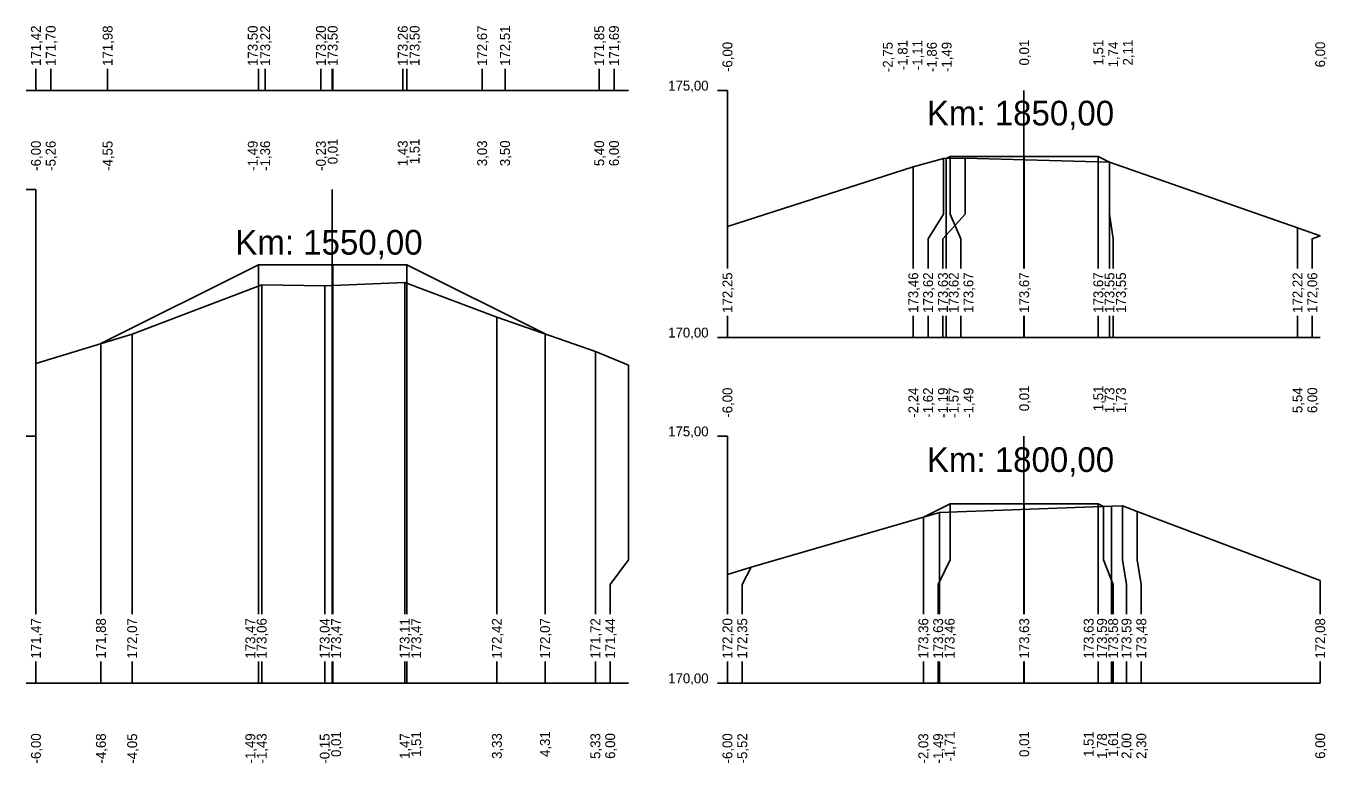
# Model space of a CAD drawing. Extents: x -614174 to -599765, y -1185887 to -1181080.
# Drawn here: x -600997.63 to -600971.29, y -1184434.96 to -1184420.03 of the extents above; entities that cross this region are included whole.
import ezdxf

# ---------------------------------------------------------------- set-up
doc = ezdxf.new("R2010")
doc.units = 0
for name, color, linetype in [('11', 7, 'Continuous'), ('16', 7, 'Continuous'), ('21', 7, 'Continuous'), ('28', 7, 'Continuous'), ('59', 7, 'Continuous'), ('8', 7, 'Continuous')]:
    doc.layers.add(name, color=color, linetype=linetype)

msp = doc.modelspace()

# ---------------------------------------------------------------- linework, layer by layer
for points in [[(-600983.427, -1184424.095), (-600979.665, -1184422.887), (-600979.052, -1184422.719), (-600978.616, -1184422.709), (-600975.693, -1184422.789), (-600971.887, -1184424.12), (-600971.427, -1184424.281)], [(-600979.001, -1184422.717), (-600978.919, -1184422.677), (-600977.419, -1184422.677), (-600975.919, -1184422.677), (-600975.695, -1184422.789)], [(-600979.001, -1184422.717), (-600979.001, -1184422.717), (-600979.001, -1184422.717)], [(-600978.919, -1184422.677), (-600978.919, -1184422.677), (-600978.919, -1184422.677)], [(-600977.419, -1184422.677), (-600977.419, -1184422.677), (-600977.419, -1184422.677)], [(-600975.919, -1184422.677), (-600975.919, -1184422.677), (-600975.919, -1184422.677)], [(-600996.111, -1184426.465), (-600992.919, -1184424.87), (-600991.419, -1184424.87), (-600989.919, -1184424.87), (-600987.12, -1184426.269)], [(-600992.919, -1184424.87), (-600992.919, -1184424.87), (-600992.919, -1184424.87)], [(-600991.419, -1184424.87), (-600991.419, -1184424.87), (-600991.419, -1184424.87)], [(-600989.919, -1184424.87), (-600989.919, -1184424.87), (-600989.919, -1184424.87)], [(-600997.427, -1184426.868), (-600995.478, -1184426.271), (-600992.856, -1184425.278), (-600991.58, -1184425.298), (-600989.96, -1184425.23), (-600988.095, -1184425.927), (-600986.101, -1184426.627), (-600985.427, -1184426.902)], [(-600996.11, -1184426.465), (-600996.111, -1184426.465), (-600996.111, -1184426.465)], [(-600983.427, -1184431.139), (-600982.948, -1184430.989), (-600979.134, -1184429.885), (-600975.649, -1184429.755), (-600975.429, -1184429.752), (-600975.13, -1184429.866), (-600971.427, -1184431.26)], [(-600979.461, -1184429.98), (-600978.919, -1184429.709), (-600977.419, -1184429.709), (-600975.919, -1184429.709), (-600975.814, -1184429.761)], [(-600978.919, -1184429.709), (-600978.919, -1184429.709), (-600978.919, -1184429.709)], [(-600977.419, -1184429.709), (-600977.419, -1184429.709), (-600977.419, -1184429.709)], [(-600975.919, -1184429.709), (-600975.919, -1184429.709), (-600975.919, -1184429.709)], [(-600979.462, -1184429.98), (-600979.461, -1184429.98), (-600979.461, -1184429.98)]]:
    msp.add_lwpolyline(points)
at = {"layer": '11'}
for points in [[(-600997.427, -1184420.902), (-600997.427, -1184421.342)], [(-600997.127, -1184420.902), (-600997.127, -1184421.342)], [(-600995.975, -1184420.902), (-600995.975, -1184421.342)], [(-600992.919, -1184420.902), (-600992.919, -1184421.342)], [(-600992.785, -1184420.902), (-600992.785, -1184421.342)], [(-600991.657, -1184420.902), (-600991.657, -1184421.342)], [(-600991.419, -1184420.902), (-600991.419, -1184421.342)], [(-600990, -1184420.902), (-600990, -1184421.342)], [(-600989.919, -1184420.902), (-600989.919, -1184421.342)], [(-600988.393, -1184420.902), (-600988.393, -1184421.342)], [(-600987.93, -1184420.902), (-600987.93, -1184421.342)], [(-600986.023, -1184420.902), (-600986.023, -1184421.342)], [(-600985.723, -1184420.902), (-600985.723, -1184421.342)], [(-600979.665, -1184422.887), (-600979.665, -1184423.842), (-600979.665, -1184424.342), (-600979.665, -1184424.944)], [(-600979.052, -1184422.719), (-600979.052, -1184423.842), (-600979.365, -1184424.342), (-600979.365, -1184424.944)], [(-600978.616, -1184422.709), (-600978.616, -1184423.842), (-600979.065, -1184424.342), (-600979.065, -1184424.944)], [(-600979.001, -1184422.717), (-600979.001, -1184423.842), (-600979.001, -1184424.342), (-600979.001, -1184424.944)], [(-600978.919, -1184422.677), (-600978.919, -1184423.842), (-600978.701, -1184424.342), (-600978.701, -1184424.944)], [(-600977.419, -1184422.677), (-600977.419, -1184423.842), (-600977.419, -1184424.342), (-600977.419, -1184424.944)], [(-600975.919, -1184422.677), (-600975.919, -1184423.842), (-600975.919, -1184424.342), (-600975.919, -1184424.944)], [(-600975.695, -1184422.789), (-600975.695, -1184423.842), (-600975.619, -1184424.342), (-600975.619, -1184424.944)], [(-600975.693, -1184422.789), (-600975.693, -1184423.842), (-600975.693, -1184424.342), (-600975.693, -1184424.944)], [(-600983.427, -1184424.095), (-600983.427, -1184423.842), (-600983.427, -1184424.342), (-600983.427, -1184424.944)], [(-600971.887, -1184424.12), (-600971.887, -1184424.342), (-600971.887, -1184424.944)], [(-600971.427, -1184424.281), (-600971.427, -1184424.281), (-600971.587, -1184424.342), (-600971.587, -1184424.944)], [(-600992.919, -1184424.87), (-600992.919, -1184430.842), (-600992.919, -1184431.342), (-600992.919, -1184431.944)], [(-600991.419, -1184424.87), (-600991.419, -1184430.842), (-600991.419, -1184431.342), (-600991.419, -1184431.944)], [(-600989.919, -1184424.87), (-600989.919, -1184430.842), (-600989.919, -1184431.342), (-600989.919, -1184431.944)], [(-600992.856, -1184425.278), (-600992.856, -1184430.842), (-600992.856, -1184431.342), (-600992.856, -1184431.944)], [(-600989.96, -1184425.23), (-600989.96, -1184430.842), (-600989.96, -1184431.342), (-600989.96, -1184431.944)], [(-600991.58, -1184425.298), (-600991.58, -1184430.842), (-600991.58, -1184431.342), (-600991.58, -1184431.944)], [(-600988.095, -1184425.927), (-600988.095, -1184430.842), (-600988.095, -1184431.342), (-600988.095, -1184431.944)], [(-600983.427, -1184425.902), (-600983.427, -1184426.342)], [(-600979.665, -1184425.902), (-600979.665, -1184426.342)], [(-600979.365, -1184425.902), (-600979.365, -1184426.342)], [(-600979.065, -1184425.902), (-600979.065, -1184426.342)], [(-600979.001, -1184425.902), (-600979.001, -1184426.342)], [(-600978.701, -1184425.902), (-600978.701, -1184426.342)], [(-600977.419, -1184425.902), (-600977.419, -1184426.342)], [(-600975.919, -1184425.902), (-600975.919, -1184426.342)], [(-600975.693, -1184425.902), (-600975.693, -1184426.342)], [(-600975.619, -1184425.902), (-600975.619, -1184426.342)], [(-600971.887, -1184425.902), (-600971.887, -1184426.342)], [(-600971.587, -1184425.902), (-600971.587, -1184426.342)], [(-600995.478, -1184426.271), (-600995.478, -1184430.842), (-600995.478, -1184431.342), (-600995.478, -1184431.944)], [(-600987.12, -1184426.269), (-600987.12, -1184430.842), (-600987.12, -1184431.342), (-600987.12, -1184431.944)], [(-600996.111, -1184426.465), (-600996.111, -1184430.842), (-600996.111, -1184431.342), (-600996.111, -1184431.944)], [(-600997.427, -1184426.868), (-600997.427, -1184430.842), (-600997.427, -1184431.342), (-600997.427, -1184431.944)], [(-600986.101, -1184426.627), (-600986.101, -1184430.842), (-600986.101, -1184431.342), (-600986.101, -1184431.944)], [(-600985.427, -1184426.902), (-600985.427, -1184430.842), (-600985.801, -1184431.342), (-600985.801, -1184431.944)], [(-600978.919, -1184429.709), (-600978.919, -1184430.842), (-600979.161, -1184431.342), (-600979.161, -1184431.944)], [(-600977.419, -1184429.709), (-600977.419, -1184430.842), (-600977.419, -1184431.342), (-600977.419, -1184431.944)], [(-600975.919, -1184429.709), (-600975.919, -1184430.842), (-600975.919, -1184431.342), (-600975.919, -1184431.944)], [(-600975.814, -1184429.761), (-600975.814, -1184430.842), (-600975.619, -1184431.342), (-600975.619, -1184431.944)], [(-600975.649, -1184429.755), (-600975.649, -1184430.842), (-600975.649, -1184431.342), (-600975.649, -1184431.944)], [(-600975.429, -1184429.752), (-600975.429, -1184430.842), (-600975.349, -1184431.342), (-600975.349, -1184431.944)], [(-600979.461, -1184429.98), (-600979.461, -1184430.842), (-600979.461, -1184431.342), (-600979.461, -1184431.944)], [(-600979.134, -1184429.885), (-600979.134, -1184430.842), (-600979.134, -1184431.342), (-600979.134, -1184431.944)], [(-600975.13, -1184429.866), (-600975.13, -1184430.842), (-600975.049, -1184431.342), (-600975.049, -1184431.944)], [(-600983.427, -1184431.139), (-600983.427, -1184430.842), (-600983.427, -1184431.342), (-600983.427, -1184431.944)], [(-600982.948, -1184430.989), (-600983.127, -1184431.342), (-600983.127, -1184431.342), (-600983.127, -1184431.944)], [(-600971.427, -1184431.26), (-600971.427, -1184431.944)], [(-600997.427, -1184432.902), (-600997.427, -1184433.342)], [(-600996.111, -1184432.902), (-600996.111, -1184433.342)], [(-600995.478, -1184432.902), (-600995.478, -1184433.342)], [(-600992.919, -1184432.902), (-600992.919, -1184433.342)], [(-600992.856, -1184432.902), (-600992.856, -1184433.342)], [(-600991.58, -1184432.902), (-600991.58, -1184433.342)], [(-600991.419, -1184432.902), (-600991.419, -1184433.342)], [(-600989.96, -1184432.902), (-600989.96, -1184433.342)], [(-600989.919, -1184432.902), (-600989.919, -1184433.342)], [(-600988.095, -1184432.902), (-600988.095, -1184433.342)], [(-600987.12, -1184432.902), (-600987.12, -1184433.342)], [(-600986.101, -1184432.902), (-600986.101, -1184433.342)], [(-600985.801, -1184432.902), (-600985.801, -1184433.342)], [(-600983.427, -1184432.902), (-600983.427, -1184433.342)], [(-600983.127, -1184432.902), (-600983.127, -1184433.342)], [(-600979.461, -1184432.902), (-600979.461, -1184433.342)], [(-600979.161, -1184432.902), (-600979.161, -1184433.342)], [(-600979.134, -1184432.902), (-600979.134, -1184433.342)], [(-600977.419, -1184432.902), (-600977.419, -1184433.342)], [(-600975.919, -1184432.902), (-600975.919, -1184433.342)], [(-600975.649, -1184432.902), (-600975.649, -1184433.342)], [(-600975.619, -1184432.902), (-600975.619, -1184433.342)], [(-600975.349, -1184432.902), (-600975.349, -1184433.342)], [(-600975.049, -1184432.902), (-600975.049, -1184433.342)], [(-600971.427, -1184432.902), (-600971.427, -1184433.342)]]:
    msp.add_lwpolyline(points, dxfattribs=at)
at = {"layer": '16'}
for p, q in [((-600997.427, -1184421.342), (-600985.427, -1184421.342)), ((-600983.427, -1184426.342), (-600971.427, -1184426.342)), ((-600997.427, -1184433.342), (-600985.427, -1184433.342)), ((-600983.427, -1184433.342), (-600971.427, -1184433.342))]:
    msp.add_line(p, q, dxfattribs=at)
for points in [[(-600975.695, -1184422.789), (-600975.695, -1184422.789), (-600975.695, -1184422.789)], [(-600987.121, -1184426.269), (-600987.12, -1184426.269), (-600987.12, -1184426.269)], [(-600975.814, -1184429.761), (-600975.814, -1184429.761), (-600975.814, -1184429.761)]]:
    msp.add_lwpolyline(points, dxfattribs=at)
at = {"layer": '21'}
for p, q in [((-600997.627, -1184421.342), (-600997.427, -1184421.342)), ((-600983.627, -1184421.342), (-600983.427, -1184421.342)), ((-600997.627, -1184423.342), (-600997.427, -1184423.342)), ((-600983.627, -1184426.342), (-600983.427, -1184426.342)), ((-600997.627, -1184428.342), (-600997.427, -1184428.342)), ((-600983.627, -1184428.342), (-600983.427, -1184428.342)), ((-600997.627, -1184433.342), (-600997.427, -1184433.342)), ((-600983.627, -1184433.342), (-600983.427, -1184433.342))]:
    msp.add_line(p, q, dxfattribs=at)
at = {"layer": '28'}
for p, q in [((-600991.427, -1184421.342), (-600991.427, -1184420.902)), ((-600977.427, -1184424.944), (-600977.427, -1184421.342)), ((-600991.427, -1184431.944), (-600991.427, -1184423.342)), ((-600977.427, -1184426.342), (-600977.427, -1184425.902)), ((-600977.427, -1184431.944), (-600977.427, -1184428.342)), ((-600991.427, -1184433.342), (-600991.427, -1184432.902)), ((-600977.427, -1184433.342), (-600977.427, -1184432.902))]:
    msp.add_line(p, q, dxfattribs=at)
at = {"layer": '8'}
for p, q in [((-600997.427, -1184421.342), (-600997.427, -1184420.902)), ((-600983.427, -1184424.944), (-600983.427, -1184421.342)), ((-600997.427, -1184431.944), (-600997.427, -1184423.342)), ((-600983.427, -1184426.342), (-600983.427, -1184425.902)), ((-600983.427, -1184431.944), (-600983.427, -1184428.342)), ((-600997.427, -1184433.342), (-600997.427, -1184432.902)), ((-600983.427, -1184433.342), (-600983.427, -1184432.902))]:
    msp.add_line(p, q, dxfattribs=at)

# ---------------------------------------------------------------- texts
at = {"layer": '16'}
for s, p in [('171,42', (-600997.327, -1184420.842)), ('171,70', (-600997.027, -1184420.842)), ('171,98', (-600995.875, -1184420.842)), ('173,50', (-600992.937, -1184420.842)), ('173,22', (-600992.685, -1184420.842)), ('173,20', (-600991.557, -1184420.842)), ('173,50', (-600991.319, -1184420.842)), ('173,26', (-600989.9, -1184420.842)), ('173,50', (-600989.66, -1184420.842)), ('172,67', (-600988.293, -1184420.842)), ('172,51', (-600987.83, -1184420.842)), ('171,85', (-600985.923, -1184420.842)), ('171,69', (-600985.623, -1184420.842)), ('172,25', (-600983.327, -1184425.842)), ('173,46', (-600979.565, -1184425.842)), ('173,62', (-600979.265, -1184425.842)), ('173,63', (-600978.965, -1184425.842)), ('173,62', (-600978.748, -1184425.842)), ('173,67', (-600978.448, -1184425.842)), ('173,67', (-600977.319, -1184425.842)), ('173,67', (-600975.819, -1184425.842)), ('173,55', (-600975.593, -1184425.842)), ('173,55', (-600975.36, -1184425.842)), ('172,22', (-600971.787, -1184425.842)), ('172,06', (-600971.487, -1184425.842)), ('171,47', (-600997.327, -1184432.842)), ('171,88', (-600996.011, -1184432.842)), ('172,07', (-600995.378, -1184432.842)), ('173,47', (-600992.986, -1184432.842)), ('173,06', (-600992.756, -1184432.842)), ('173,04', (-600991.48, -1184432.842)), ('173,47', (-600991.25, -1184432.842)), ('173,11', (-600989.86, -1184432.842)), ('173,47', (-600989.628, -1184432.842)), ('172,42', (-600987.995, -1184432.842)), ('172,07', (-600987.02, -1184432.842)), ('171,72', (-600986.001, -1184432.842)), ('171,44', (-600985.701, -1184432.842)), ('172,20', (-600983.327, -1184432.842)), ('172,35', (-600983.027, -1184432.842)), ('173,36', (-600979.361, -1184432.842)), ('173,63', (-600979.061, -1184432.842)), ('173,46', (-600978.829, -1184432.842)), ('173,63', (-600977.319, -1184432.842)), ('173,63', (-600976.014, -1184432.842)), ('173,59', (-600975.744, -1184432.842)), ('173,58', (-600975.519, -1184432.842)), ('173,59', (-600975.249, -1184432.842)), ('173,48', (-600974.949, -1184432.842)), ('172,08', (-600971.327, -1184432.842))]:
    msp.add_text(s, height=0.2, rotation=90, dxfattribs=at).set_placement(p)
at = {"layer": '21'}
for s, p in [('175,00', (-600984.627, -1184421.342)), ('170,00', (-600984.627, -1184426.342)), ('175,00', (-600984.627, -1184428.342)), ('170,00', (-600984.627, -1184433.342))]:
    msp.add_text(s, height=0.2, dxfattribs=at).set_placement(p)
at = {"layer": '28'}
for s, p in [('Km: 1850,00', (-600979.39, -1184422.048)), ('Km: 1550,00', (-600993.39, -1184424.663)), ('Km: 1800,00', (-600979.39, -1184429.063))]:
    msp.add_text(s, height=0.5, dxfattribs=at).set_placement(p)
at = {"layer": '59'}
for s, p in [('-6,00', (-600983.327, -1184420.965)), ('-2,75', (-600980.081, -1184420.968)), ('-1,81', (-600979.781, -1184420.927)), ('-1,11', (-600979.481, -1184420.927)), ('-1,86', (-600979.189, -1184420.966)), ('-1,49', (-600978.889, -1184420.966)), ('0,01', (-600977.319, -1184420.834)), ('1,51', (-600975.819, -1184420.834)), ('1,74', (-600975.519, -1184420.872)), ('2,11', (-600975.221, -1184420.834)), ('6,00', (-600971.327, -1184420.872)), ('-6,00', (-600997.327, -1184422.965)), ('-5,26', (-600997.027, -1184422.966)), ('-4,55', (-600995.875, -1184422.968)), ('-1,49', (-600992.937, -1184422.966)), ('-1,36', (-600992.685, -1184422.966)), ('-0,23', (-600991.557, -1184422.966)), ('0,01', (-600991.319, -1184422.834)), ('1,43', (-600989.9, -1184422.873)), ('1,51', (-600989.66, -1184422.834)), ('3,03', (-600988.293, -1184422.873)), ('3,50', (-600987.83, -1184422.872)), ('5,40', (-600985.923, -1184422.872)), ('6,00', (-600985.623, -1184422.872)), ('-6,00', (-600983.327, -1184427.965)), ('-2,24', (-600979.565, -1184427.965)), ('-1,62', (-600979.265, -1184427.964)), ('-1,19', (-600978.965, -1184427.966)), ('-1,57', (-600978.748, -1184427.966)), ('-1,49', (-600978.448, -1184427.966)), ('0,01', (-600977.319, -1184427.834)), ('1,51', (-600975.819, -1184427.834)), ('1,73', (-600975.593, -1184427.873)), ('1,73', (-600975.36, -1184427.873)), ('5,54', (-600971.787, -1184427.872)), ('6,00', (-600971.487, -1184427.872)), ('-6,00', (-600997.327, -1184434.965)), ('-4,68', (-600996.011, -1184434.966)), ('-4,05', (-600995.378, -1184434.968)), ('-1,49', (-600992.986, -1184434.966)), ('-1,43', (-600992.756, -1184434.966)), ('-0,15', (-600991.48, -1184434.968)), ('0,01', (-600991.25, -1184434.834)), ('1,47', (-600989.86, -1184434.873)), ('1,51', (-600989.628, -1184434.834)), ('3,33', (-600987.995, -1184434.873)), ('4,31', (-600987.02, -1184434.834)), ('5,33', (-600986.001, -1184434.873)), ('6,00', (-600985.701, -1184434.872)), ('-6,00', (-600983.327, -1184434.965)), ('-5,52', (-600983.027, -1184434.964)), ('-2,03', (-600979.361, -1184434.966)), ('-1,49', (-600979.061, -1184434.966)), ('-1,71', (-600978.829, -1184434.927)), ('0,01', (-600977.319, -1184434.834)), ('1,51', (-600976.014, -1184434.834)), ('1,78', (-600975.744, -1184434.873)), ('1,61', (-600975.519, -1184434.834)), ('2,00', (-600975.249, -1184434.872)), ('2,30', (-600974.949, -1184434.872)), ('6,00', (-600971.327, -1184434.872))]:
    msp.add_text(s, height=0.2, rotation=90, dxfattribs=at).set_placement(p)

doc.saveas('drawing.dxf')
